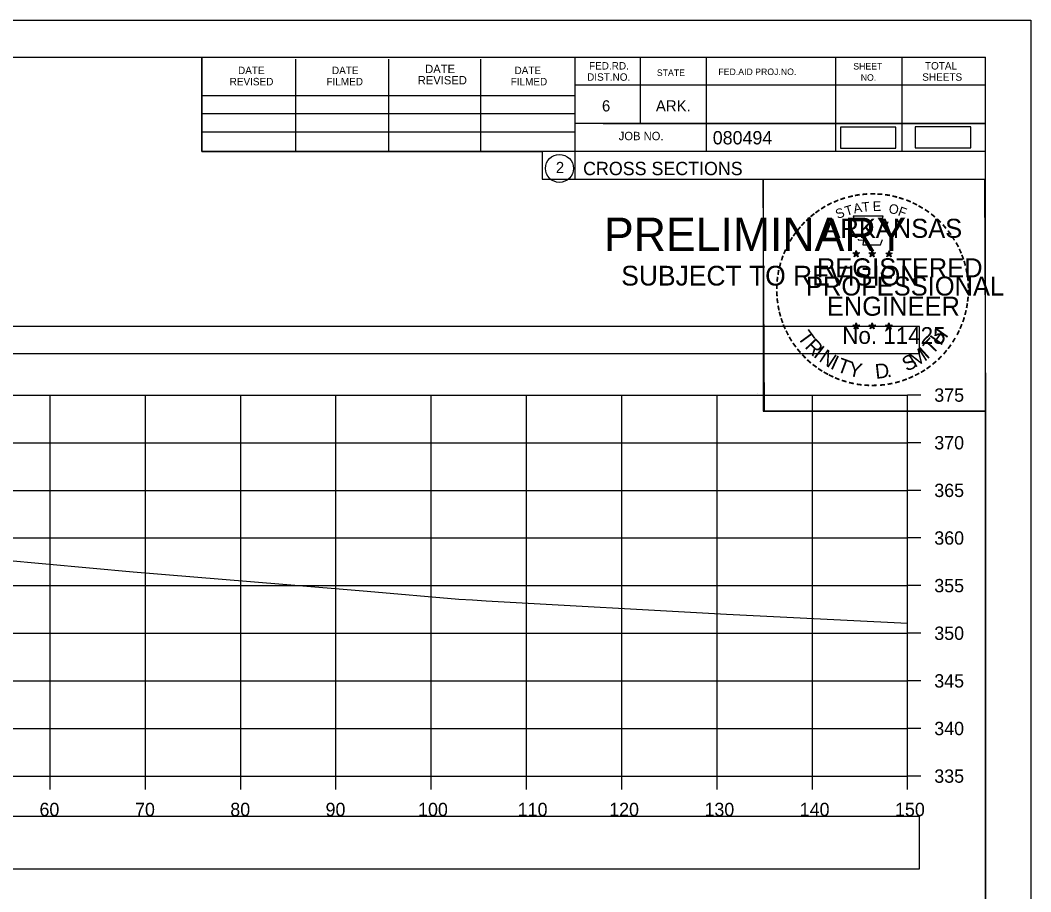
# Model space of a CAD drawing. Extents: x 1376273 to 1384221, y 378927 to 384592.
# Drawn here: x 1377114.6 to 1377220.7, y 380873.7 to 380965.2 of the extents above; entities that cross this region are included whole.
import ezdxf

# ---------------------------------------------------------------- set-up
doc = ezdxf.new("R2010")
doc.units = 0
for name, color, linetype in [('R_Axis', 7, 'Continuous'), ('R_Axis Annot', 7, 'Continuous'), ('R_Border', 7, 'Continuous'), ('R_Border PE', 7, 'Continuous'), ('R_Border Prem', 7, 'Continuous'), ('R_Drive', 7, 'Continuous'), ('R_Exist Surface', 7, 'Continuous'), ('R_Grid', 7, 'Continuous'), ('R_No Plot', 7, 'Continuous')]:
    doc.layers.add(name, color=color, linetype=linetype)

msp = doc.modelspace()

# ---------------------------------------------------------------- linework, layer by layer
at = {"layer": 'R_Axis'}
for p, q in [((1377207.77, 380885.83), (1377207.77, 380925.83)), ((1377209.17, 380925.83), (1377207.77, 380925.83)), ((1377209.17, 380920.83), (1377207.77, 380920.83)), ((1377209.17, 380915.83), (1377207.77, 380915.83)), ((1377209.17, 380910.83), (1377207.77, 380910.83)), ((1377209.17, 380905.83), (1377207.77, 380905.83)), ((1377209.17, 380900.83), (1377207.77, 380900.83)), ((1377209.17, 380895.83), (1377207.77, 380895.83)), ((1377209.17, 380890.83), (1377207.77, 380890.83)), ((1376907.77, 380885.83), (1377207.77, 380885.83)), ((1377117.77, 380884.43), (1377117.77, 380885.83)), ((1377127.77, 380884.43), (1377127.77, 380885.83)), ((1377137.77, 380884.43), (1377137.77, 380885.83)), ((1377147.77, 380884.43), (1377147.77, 380885.83)), ((1377157.77, 380884.43), (1377157.77, 380885.83)), ((1377167.77, 380884.43), (1377167.77, 380885.83)), ((1377177.77, 380884.43), (1377177.77, 380885.83)), ((1377187.77, 380884.43), (1377187.77, 380885.83)), ((1377197.77, 380884.43), (1377197.77, 380885.83)), ((1377207.77, 380884.43), (1377207.77, 380885.83)), ((1377209.17, 380885.83), (1377207.77, 380885.83))]:
    msp.add_line(p, q, dxfattribs=at)
at = {"layer": 'R_Axis Annot'}
for points in [[(1376907.2, 380930.21), (1377209.01, 380930.21), (1377209.01, 380933.03), (1376907.2, 380933.03)], [(1376907.2, 380876.08), (1377209.01, 380876.08), (1377209.01, 380881.6), (1376907.2, 380881.6)]]:
    msp.add_lwpolyline(points, close=True, dxfattribs=at)
at = {"layer": 'R_Border'}
for p, q in [((1376899.77, 380961.29), (1377215.95, 380961.29)), ((1377133.69, 380951.41), (1377133.69, 380961.29)), ((1377143.55, 380951.41), (1377143.55, 380961.09)), ((1377153.31, 380951.41), (1377153.31, 380961.09)), ((1377162.99, 380951.41), (1377162.99, 380961.09)), ((1377172.85, 380961.29), (1377172.85, 380948.49)), ((1377179.69, 380961.29), (1377179.69, 380954.35)), ((1377186.63, 380961.29), (1377186.63, 380951.41)), ((1377200.21, 380961.29), (1377200.21, 380951.41)), ((1377207.15, 380961.29), (1377207.15, 380951.41)), ((1377215.95, 380755.83), (1377215.95, 380961.29)), ((1377215.95, 380958.35), (1377172.85, 380958.35)), ((1377215.95, 380958.37), (1377215.95, 380958.37)), ((1377133.69, 380957.27), (1377172.85, 380957.27)), ((1377133.69, 380955.41), (1377172.85, 380955.41)), ((1377215.95, 380954.35), (1377172.85, 380954.35)), ((1377175.81, 380954.35), (1377215.95, 380954.35)), ((1377133.69, 380951.41), (1377133.69, 380953.47)), ((1377133.69, 380953.47), (1377172.85, 380953.47)), ((1377215.95, 380951.41), (1377133.69, 380951.41)), ((1377172.85, 380948.49), (1377215.95, 380948.49))]:
    msp.add_line(p, q, dxfattribs=at)
msp.add_circle((1377171.23, 380949.63), 1.47, dxfattribs=at)
at = {"layer": 'R_Border PE'}
for p, q in [((1377202.03, 380940.75), (1377202.38, 380940.64)), ((1377202.03, 380940.75), (1377202.29, 380940.7)), ((1377202.03, 380940.75), (1377202.27, 380940.63)), ((1377202.17, 380940.34), (1377202.38, 380940.64)), ((1377202.17, 380940.34), (1377202.29, 380940.58)), ((1377202.17, 380940.34), (1377202.38, 380940.56)), ((1377202.38, 380941), (1377202.34, 380940.75)), ((1377202.38, 380940.64), (1377202.38, 380941)), ((1377202.38, 380941), (1377202.43, 380940.75)), ((1377202.73, 380940.75), (1377202.38, 380940.64)), ((1377202.59, 380940.34), (1377202.38, 380940.64)), ((1377202.59, 380940.34), (1377202.38, 380940.55)), ((1377202.73, 380940.75), (1377202.44, 380940.7)), ((1377202.59, 380940.34), (1377202.46, 380940.63)), ((1377202.73, 380940.75), (1377202.52, 380940.65)), ((1377203.7, 380940.75), (1377204.05, 380940.64)), ((1377203.7, 380940.75), (1377203.96, 380940.7)), ((1377203.7, 380940.75), (1377203.94, 380940.63)), ((1377203.84, 380940.34), (1377204.05, 380940.64)), ((1377203.84, 380940.34), (1377203.96, 380940.58)), ((1377203.84, 380940.34), (1377204.05, 380940.56)), ((1377204.05, 380941), (1377204.01, 380940.75)), ((1377204.05, 380940.64), (1377204.05, 380941)), ((1377204.05, 380941), (1377204.1, 380940.75)), ((1377204.4, 380940.75), (1377204.05, 380940.64)), ((1377204.26, 380940.34), (1377204.05, 380940.64)), ((1377204.26, 380940.34), (1377204.05, 380940.55)), ((1377204.4, 380940.75), (1377204.11, 380940.7)), ((1377204.26, 380940.34), (1377204.13, 380940.63)), ((1377204.4, 380940.75), (1377204.19, 380940.65)), ((1377205.47, 380940.74), (1377205.82, 380940.62)), ((1377205.47, 380940.74), (1377205.72, 380940.69)), ((1377205.47, 380940.74), (1377205.7, 380940.61)), ((1377205.6, 380940.33), (1377205.82, 380940.62)), ((1377205.6, 380940.33), (1377205.73, 380940.57)), ((1377205.6, 380940.33), (1377205.81, 380940.54)), ((1377205.82, 380940.99), (1377205.77, 380940.74)), ((1377206.03, 380940.33), (1377205.81, 380940.54)), ((1377205.82, 380940.62), (1377205.82, 380940.99)), ((1377205.82, 380940.99), (1377205.86, 380940.74)), ((1377206.16, 380940.74), (1377205.82, 380940.62)), ((1377206.03, 380940.33), (1377205.82, 380940.62)), ((1377206.16, 380940.74), (1377205.88, 380940.69)), ((1377206.03, 380940.33), (1377205.89, 380940.62)), ((1377206.16, 380940.74), (1377205.96, 380940.63)), ((1377202.03, 380933.17), (1377202.38, 380933.06)), ((1377202.03, 380933.17), (1377202.28, 380933.13)), ((1377202.03, 380933.17), (1377202.27, 380933.05)), ((1377202.16, 380932.77), (1377202.38, 380933.06)), ((1377202.16, 380932.77), (1377202.29, 380933.01)), ((1377202.16, 380932.77), (1377202.38, 380932.98)), ((1377202.38, 380933.43), (1377202.34, 380933.18)), ((1377202.38, 380933.06), (1377202.38, 380933.43)), ((1377202.38, 380933.43), (1377202.43, 380933.18)), ((1377202.72, 380933.17), (1377202.38, 380933.06)), ((1377202.59, 380932.77), (1377202.38, 380933.06)), ((1377202.59, 380932.77), (1377202.38, 380932.98)), ((1377202.72, 380933.17), (1377202.44, 380933.13)), ((1377202.59, 380932.77), (1377202.45, 380933.06)), ((1377202.72, 380933.17), (1377202.52, 380933.07)), ((1377203.7, 380933.17), (1377204.05, 380933.06)), ((1377203.7, 380933.17), (1377203.95, 380933.13)), ((1377203.7, 380933.17), (1377203.93, 380933.05)), ((1377203.83, 380932.77), (1377204.05, 380933.06)), ((1377203.83, 380932.77), (1377203.96, 380933.01)), ((1377203.83, 380932.77), (1377204.04, 380932.98)), ((1377204.05, 380933.43), (1377204.01, 380933.18)), ((1377204.26, 380932.77), (1377204.04, 380932.98)), ((1377204.05, 380933.06), (1377204.05, 380933.43)), ((1377204.05, 380933.43), (1377204.1, 380933.18)), ((1377204.39, 380933.17), (1377204.05, 380933.06)), ((1377204.26, 380932.77), (1377204.05, 380933.06)), ((1377204.39, 380933.17), (1377204.11, 380933.13)), ((1377204.26, 380932.77), (1377204.12, 380933.06)), ((1377204.39, 380933.17), (1377204.19, 380933.07)), ((1377205.46, 380933.16), (1377205.81, 380933.05)), ((1377205.46, 380933.16), (1377205.72, 380933.12)), ((1377205.46, 380933.16), (1377205.7, 380933.04)), ((1377205.6, 380932.76), (1377205.81, 380933.05)), ((1377205.6, 380932.76), (1377205.72, 380933)), ((1377205.6, 380932.76), (1377205.81, 380932.97)), ((1377205.81, 380933.42), (1377205.77, 380933.17)), ((1377205.81, 380933.05), (1377205.81, 380933.42)), ((1377205.81, 380933.42), (1377205.86, 380933.17)), ((1377206.16, 380933.16), (1377205.81, 380933.05)), ((1377206.03, 380932.76), (1377205.81, 380933.05)), ((1377206.03, 380932.76), (1377205.81, 380932.97)), ((1377206.16, 380933.16), (1377205.87, 380933.12)), ((1377206.03, 380932.76), (1377205.89, 380933.05)), ((1377206.16, 380933.16), (1377205.96, 380933.06))]:
    msp.add_line(p, q, dxfattribs=at)
for points in [[(1377202.07, 380944.63), (1377202.34, 380943.8)], [(1377205.58, 380943.7), (1377205.73, 380943.99), (1377205.04, 380943.96), (1377205.19, 380944.63), (1377202.07, 380944.63)], [(1377202.57, 380942.2), (1377202.57, 380942.12), (1377203.13, 380942.1), (1377203.07, 380941.62), (1377204.94, 380941.62), (1377205.15, 380942.16)], [(1377202.38, 380941), (1377202.59, 380940.34), (1377202.03, 380940.75), (1377202.73, 380940.75), (1377202.17, 380940.34), (1377202.38, 380941)], [(1377204.05, 380941), (1377204.26, 380940.34), (1377203.7, 380940.75), (1377204.4, 380940.75), (1377203.84, 380940.34), (1377204.05, 380941)], [(1377205.82, 380940.99), (1377206.03, 380940.33), (1377205.47, 380940.74), (1377206.16, 380940.74), (1377205.6, 380940.33), (1377205.82, 380940.99)], [(1377202.38, 380933.43), (1377202.59, 380932.77), (1377202.03, 380933.17), (1377202.72, 380933.17), (1377202.16, 380932.77), (1377202.38, 380933.43)], [(1377204.05, 380933.43), (1377204.26, 380932.77), (1377203.7, 380933.17), (1377204.39, 380933.17), (1377203.83, 380932.77), (1377204.05, 380933.43)], [(1377205.81, 380933.42), (1377206.03, 380932.76), (1377205.46, 380933.16), (1377206.16, 380933.16), (1377205.6, 380932.76), (1377205.81, 380933.42)]]:
    msp.add_lwpolyline(points, dxfattribs=at)
for centre, radius in [((1377202.38, 380940.64), 0.172), ((1377202.38, 380940.64), 0.145), ((1377202.38, 380940.64), 0.116), ((1377202.38, 380940.64), 0.0991), ((1377202.38, 380940.64), 0.0747), ((1377202.38, 380940.64), 0.0495), ((1377202.38, 380940.64), 0.0296), ((1377204.05, 380940.64), 0.172), ((1377204.05, 380940.64), 0.145), ((1377204.05, 380940.64), 0.116), ((1377204.05, 380940.64), 0.0991), ((1377204.05, 380940.64), 0.0747), ((1377204.05, 380940.64), 0.0495), ((1377204.05, 380940.64), 0.0296), ((1377205.81, 380940.62), 0.172), ((1377205.81, 380940.62), 0.145), ((1377205.81, 380940.62), 0.116), ((1377205.81, 380940.62), 0.0991), ((1377205.81, 380940.62), 0.0747), ((1377205.81, 380940.62), 0.0495), ((1377205.81, 380940.62), 0.0296), ((1377202.38, 380933.06), 0.172), ((1377202.38, 380933.06), 0.145), ((1377202.38, 380933.06), 0.116), ((1377202.38, 380933.06), 0.0991), ((1377202.38, 380933.06), 0.0747), ((1377202.38, 380933.06), 0.0495), ((1377202.38, 380933.06), 0.0296), ((1377204.05, 380933.06), 0.172), ((1377204.05, 380933.06), 0.145), ((1377204.05, 380933.06), 0.116), ((1377204.05, 380933.06), 0.0991), ((1377204.05, 380933.06), 0.0747), ((1377204.05, 380933.06), 0.0495), ((1377204.05, 380933.06), 0.0296), ((1377205.81, 380933.05), 0.172), ((1377205.81, 380933.05), 0.145), ((1377205.81, 380933.05), 0.116), ((1377205.81, 380933.05), 0.0991), ((1377205.81, 380933.05), 0.0747), ((1377205.81, 380933.05), 0.0495), ((1377205.81, 380933.05), 0.0296)]:
    msp.add_circle(centre, radius, dxfattribs=at)
at = {"layer": 'R_Drive'}
for points in [[(1377200.72, 380951.77), (1377206.55, 380951.77), (1377206.55, 380953.96), (1377200.72, 380953.96)], [(1377208.55, 380951.79), (1377214.39, 380951.79), (1377214.39, 380953.98), (1377208.55, 380953.98)]]:
    msp.add_lwpolyline(points, close=True, dxfattribs=at)
at = {"layer": 'R_Exist Surface'}
msp.add_lwpolyline([(1377108.13, 380908.97), (1377117.32, 380908.1), (1377126.47, 380907.27), (1377142.19, 380905.97), (1377151.03, 380905.23), (1377160.68, 380904.42), (1377162.1, 380904.32), (1377163.54, 380904.24), (1377188.76, 380902.82), (1377207.77, 380901.9)], dxfattribs=at)
at = {"layer": 'R_Grid'}
for p, q in [((1376907.77, 380925.83), (1377207.77, 380925.83)), ((1376907.77, 380925.83), (1377207.77, 380925.83)), ((1377117.77, 380885.83), (1377117.77, 380925.83)), ((1377117.77, 380885.83), (1377117.77, 380925.83)), ((1377127.77, 380885.83), (1377127.77, 380925.83)), ((1377127.77, 380885.83), (1377127.77, 380925.83)), ((1377137.77, 380885.83), (1377137.77, 380925.83)), ((1377137.77, 380885.83), (1377137.77, 380925.83)), ((1377147.77, 380885.83), (1377147.77, 380925.83)), ((1377147.77, 380885.83), (1377147.77, 380925.83)), ((1377157.77, 380885.83), (1377157.77, 380925.83)), ((1377157.77, 380885.83), (1377157.77, 380925.83)), ((1377167.77, 380885.83), (1377167.77, 380925.83)), ((1377167.77, 380885.83), (1377167.77, 380925.83)), ((1377177.77, 380885.83), (1377177.77, 380925.83)), ((1377177.77, 380885.83), (1377177.77, 380925.83)), ((1377187.77, 380885.83), (1377187.77, 380925.83)), ((1377187.77, 380885.83), (1377187.77, 380925.83)), ((1377197.77, 380885.83), (1377197.77, 380925.83)), ((1377197.77, 380885.83), (1377197.77, 380925.83)), ((1377207.77, 380885.83), (1377207.77, 380925.83)), ((1377207.77, 380885.83), (1377207.77, 380925.83)), ((1376907.77, 380920.83), (1377207.77, 380920.83)), ((1376907.77, 380920.83), (1377207.77, 380920.83)), ((1376907.77, 380915.83), (1377207.77, 380915.83)), ((1376907.77, 380915.83), (1377207.77, 380915.83)), ((1376907.77, 380910.83), (1377207.77, 380910.83)), ((1376907.77, 380910.83), (1377207.77, 380910.83)), ((1376907.77, 380905.83), (1377207.77, 380905.83)), ((1376907.77, 380905.83), (1377207.77, 380905.83)), ((1376907.77, 380900.83), (1377207.77, 380900.83)), ((1376907.77, 380900.83), (1377207.77, 380900.83)), ((1376907.77, 380895.83), (1377207.77, 380895.83)), ((1376907.77, 380895.83), (1377207.77, 380895.83)), ((1376907.77, 380890.83), (1377207.77, 380890.83)), ((1376907.77, 380890.83), (1377207.77, 380890.83)), ((1376907.77, 380885.83), (1377207.77, 380885.83)), ((1376907.77, 380885.83), (1377207.77, 380885.83))]:
    msp.add_line(p, q, dxfattribs=at)
at = {"layer": 'R_No Plot'}
for p, q in [((1376887.37, 380965.19), (1377220.7, 380965.19)), ((1377191.98, 380926.04), (1377191.98, 380926.04))]:
    msp.add_line(p, q, dxfattribs=at)
for points in [[(1376887.36, 380965.19), (1377220.7, 380965.19), (1377220.7, 380751.85), (1376887.36, 380751.85)], [(1377133.69, 380961.29), (1377133.69, 380951.41), (1377169.42, 380951.41), (1377169.42, 380948.49), (1377192.62, 380948.49), (1377192.62, 380924.16), (1377215.95, 380924.16), (1377215.95, 380755.83), (1376899.77, 380755.83), (1376899.77, 380961.29)], [(1377192.62, 380948.49), (1377215.83, 380948.49), (1377215.95, 380924.16), (1377192.74, 380924.16)]]:
    msp.add_lwpolyline(points, close=True, dxfattribs=at)

# ---------------------------------------------------------------- texts
at = {"layer": 'R_Axis Annot'}
for s, p in [('375', (1377210.57, 380925.13)), ('370', (1377210.57, 380920.13)), ('365', (1377210.57, 380915.13)), ('360', (1377210.57, 380910.13)), ('355', (1377210.57, 380905.13)), ('350', (1377210.57, 380900.13)), ('345', (1377210.57, 380895.13)), ('340', (1377210.57, 380890.13)), ('335', (1377210.57, 380885.13)), ('60', (1377116.65, 380881.63)), ('70', (1377126.68, 380881.63)), ('80', (1377136.68, 380881.63)), ('90', (1377146.68, 380881.63)), ('100', (1377156.39, 380881.63)), ('110', (1377166.85, 380881.63)), ('120', (1377176.45, 380881.63)), ('130', (1377186.45, 380881.63)), ('140', (1377196.45, 380881.63)), ('150', (1377206.45, 380881.63))]:
    msp.add_text(s, height=1.4, dxfattribs=at).set_placement(p)
at = {"layer": 'R_Border'}
for s, height, p in [('DATE', 0.782, (1377137.49, 380959.53)), ('DATE', 0.782, (1377147.35, 380959.53)), ('DATE', 0.879, (1377157.13, 380959.63)), ('DATE', 0.782, (1377166.51, 380959.53)), ('FED.RD.', 0.782, (1377174.33, 380960.01)), ('SHEET', 0.684, (1377202.07, 380960.01)), ('TOTAL', 0.782, (1377209.59, 380960.01)), ('REVISED', 0.879, (1377156.35, 380958.45)), ('DIST.NO.', 0.782, (1377174.13, 380958.83)), ('STATE', 0.684, (1377181.45, 380959.33)), ('FED.AID PROJ.NO.', 0.684, (1377187.91, 380959.43)), ('NO.', 0.684, (1377202.85, 380958.83)), ('SHEETS', 0.782, (1377209.31, 380958.83)), ('REVISED', 0.782, (1377136.61, 380958.35)), ('FILMED', 0.782, (1377146.77, 380958.35)), ('FILMED', 0.782, (1377166.11, 380958.35)), ('6', 1.17, (1377175.69, 380955.61)), ('ARK.', 1.172, (1377181.35, 380955.61)), ('JOB NO.', 0.879, (1377177.45, 380952.59)), ('080494', 1.4, (1377187.32, 380952.15)), ('2', 1.17, (1377170.85, 380949.14)), ('CROSS SECTIONS', 1.4, (1377173.71, 380948.92))]:
    msp.add_text(s, height=height, rotation=360, dxfattribs=at).set_placement(p)
at = {"layer": 'R_Border PE'}
for s, height, rotation, p in [('-', 1.6, 19.1761, (1377200.82, 380945.75)), ('-', 1.6, 13.6301, (1377201.57, 380945.99)), ('-', 1.6, 10.2193, (1377202.25, 380946.16)), ('-', 1.6, 5.8968, (1377202.98, 380946.27)), ('-', 1.6, 0.1862, (1377203.75, 380946.34)), ('-', 1.6, 357.743, (1377204.47, 380946.32)), ('-', 1.6, 352.1617, (1377205.22, 380946.27)), ('-', 1.6, 347.2049, (1377205.94, 380946.15)), ('-', 1.6, 342.3362, (1377206.57, 380946)), ('-', 1.6, 34.0636, (1377198.96, 380944.8)), ('-', 1.6, 28.7918, (1377199.55, 380945.17)), ('-', 1.6, 24.3072, (1377200.19, 380945.48)), ('S', 1, 21.594, (1377200.43, 380944.3)), ('T', 1, 16.4036, (1377201.34, 380944.63)), ('A', 1, 11.2132, (1377202.17, 380944.89)), ('T', 1, 6.0228, (1377203.02, 380945.05)), ('E', 1, 0.8323, (1377204.12, 380945.16)), ('O', 1, 350.4515, (1377205.73, 380944.95)), ('F', 1, 340.0707, (1377206.68, 380944.72)), ('-', 1.6, 337.8551, (1377207.31, 380945.78)), ('-', 1.6, 334.1211, (1377207.94, 380945.51)), ('-', 1.6, 329.6409, (1377208.52, 380945.22)), ('-', 1.6, 42.9622, (1377197.47, 380943.61)), ('-', 1.6, 38.9507, (1377197.9, 380944.02)), ('-', 1.6, 36.2317, (1377198.38, 380944.4)), ('-', 1.6, 325.8627, (1377209.16, 380944.86)), ('-', 1.6, 320.5297, (1377209.77, 380944.44)), ('-', 1.6, 315.5786, (1377210.37, 380943.95)), ('-', 1.6, 50.6142, (1377196.62, 380942.64)), ('-', 1.6, 48.423, (1377197.02, 380943.13)), ('ARKANSAS', 2, 360, (1377198.93, 380942.34)), ('-', 1.6, 309.8797, (1377210.94, 380943.4)), ('-', 1.6, 58.0706, (1377195.88, 380941.55)), ('-', 1.6, 54.2325, (1377196.21, 380942.08)), ('-', 1.6, 306.6522, (1377211.46, 380942.8)), ('-', 1.4, 303.6753, (1377211.95, 380942.23)), ('-', 1.6, 62.8713, (1377195.57, 380940.93)), ('-', 1.6, 299.6684, (1377212.27, 380941.62)), ('-', 1.6, 294.6628, (1377212.59, 380941.01)), ('-', 1.6, 72.3945, (1377195.09, 380939.69)), ('-', 1.6, 67.7743, (1377195.31, 380940.32)), ('REGISTERED', 2, 360, (1377198.25, 380938.19)), ('DWB', 0.01, 360, (1377202.37, 380940.63)), ('DWB', 0.01, 360, (1377204.04, 380940.63)), ('DWB', 0.01, 360, (1377205.8, 380940.62)), ('-', 1.6, 290.5728, (1377212.85, 380940.43)), ('-', 1.6, 75.461, (1377194.89, 380938.98)), ('-', 1.6, 285.1233, (1377213.08, 380939.85)), ('-', 1.6, 280.5493, (1377213.28, 380939.11)), ('-', 1.6, 85.1863, (1377194.68, 380937.58)), ('-', 1.6, 81.2013, (1377194.76, 380938.27)), ('PROFESSIONAL', 2, 360, (1377197.1, 380936.28)), ('-', 1.6, 276.5962, (1377213.44, 380938.34)), ('-', 1.6, 89.0622, (1377194.66, 380936.87)), ('-', 1.6, 274.3301, (1377213.5, 380937.62)), ('-', 1.6, 94.1959, (1377194.69, 380936.15)), ('-', 1.6, 98.9479, (1377194.77, 380935.48)), ('ENGINEER', 2, 360, (1377199.29, 380934.16)), ('-', 1.6, 263.5172, (1377213.52, 380936.32)), ('-', 1.6, 269.9407, (1377213.54, 380936.99)), ('-', 1.6, 101.7149, (1377194.9, 380934.75)), ('-', 1.6, 260.9953, (1377213.45, 380935.67)), ('-', 1.6, 105.4578, (1377195.06, 380934.15)), ('-', 1.6, 109.0874, (1377195.28, 380933.52)), ('-', 1.6, 252.8681, (1377213.16, 380934.27)), ('-', 1.6, 255.7626, (1377213.34, 380934.99)), ('-', 1.6, 114.0643, (1377195.53, 380932.93)), ('T', 1.54, 306.0406, (1377196.14, 380931.9)), ('No. 11425', 1.757, 360, (1377200.91, 380931.21)), ('DWB', 0.01, 360, (1377202.36, 380933.06)), ('DWB', 0.01, 360, (1377204.03, 380933.06)), ('DWB', 0.01, 360, (1377205.8, 380933.05)), ('H', 1.54, 54.6088, (1377211.26, 380930.94)), ('-', 1.6, 247.8887, (1377212.93, 380933.6)), ('-', 1.6, 115.7289, (1377195.84, 380932.31)), ('-', 1.6, 120.4471, (1377196.19, 380931.72)), ('R', 1.54, 314.005, (1377196.9, 380930.85)), ('T', 1.54, 46.6444, (1377210.37, 380929.99)), ('-', 1.6, 239.0712, (1377212.28, 380932.22)), ('-', 1.6, 244.6197, (1377212.67, 380932.97)), ('-', 1.6, 125.8934, (1377196.6, 380931.16)), ('-', 1.6, 130.7181, (1377197.06, 380930.61)), ('I', 1.54, 321.9694, (1377197.8, 380929.92)), ('N', 1.54, 326.5002, (1377198.37, 380929.45)), ('M', 1.54, 32.6563, (1377208.52, 380928.67)), ('I', 1.54, 42.1136, (1377209.81, 380929.52)), ('-', 1.6, 231.2538, (1377211.45, 380931)), ('-', 1.6, 233.8452, (1377211.88, 380931.56)), ('-', 1.6, 134.2238, (1377197.58, 380930.07)), ('-', 1.6, 138.9338, (1377198.1, 380929.6)), ('I', 1.54, 335.3603, (1377199.57, 380928.66)), ('T', 1.54, 339.8912, (1377200.24, 380928.34)), ('S', 1.54, 26.9312, (1377207.68, 380928.26)), ('-', 1.6, 225.7653, (1377210.97, 380930.43)), ('-', 1.6, 144.6463, (1377198.66, 380929.2)), ('-', 1.6, 148.0898, (1377199.22, 380928.82)), ('Y', 1.54, 347.8556, (1377201.45, 380927.89)), ('D', 1.54, 6.3969, (1377204.44, 380927.53)), ('-', 1.6, 212.2491, (1377209.36, 380929.06)), ('-', 1.6, 215.7363, (1377209.9, 380929.45)), ('-', 1.6, 221.0851, (1377210.44, 380929.92)), ('-', 1.6, 151.5704, (1377199.8, 380928.5)), ('-', 1.6, 154.6002, (1377200.32, 380928.25)), ('-', 1.6, 158.5612, (1377200.94, 380928)), ('-', 1.6, 162.7983, (1377201.63, 380927.79)), ('.', 1.54, 13.7642, (1377205.63, 380927.66)), ('-', 1.6, 200.7184, (1377207.56, 380928.13)), ('-', 1.6, 204.2516, (1377208.18, 380928.4)), ('-', 1.6, 207.3568, (1377208.8, 380928.72)), ('-', 1.6, 167.5555, (1377202.35, 380927.62)), ('-', 1.6, 173.1155, (1377203.12, 380927.51)), ('-', 1.6, 176.5183, (1377203.87, 380927.46)), ('-', 1.6, 181.5918, (1377204.61, 380927.48)), ('-', 1.6, 185.8167, (1377205.42, 380927.55)), ('-', 1.6, 191.2858, (1377206.15, 380927.69)), ('-', 1.6, 195.4743, (1377206.88, 380927.88))]:
    msp.add_text(s, height=height, rotation=rotation, dxfattribs=at).set_placement(p)
at = {"layer": 'R_Border Prem'}
for s, height, p in [('PRELIMINARY', 3.5, (1377175.9, 380940.96)), ('DWB', 0.01, (1377176.64, 380942.8)), ('SUBJECT TO REVISION', 2.0751, (1377177.71, 380937.33))]:
    msp.add_text(s, height=height, rotation=360, dxfattribs=at).set_placement(p)

doc.saveas('drawing.dxf')
